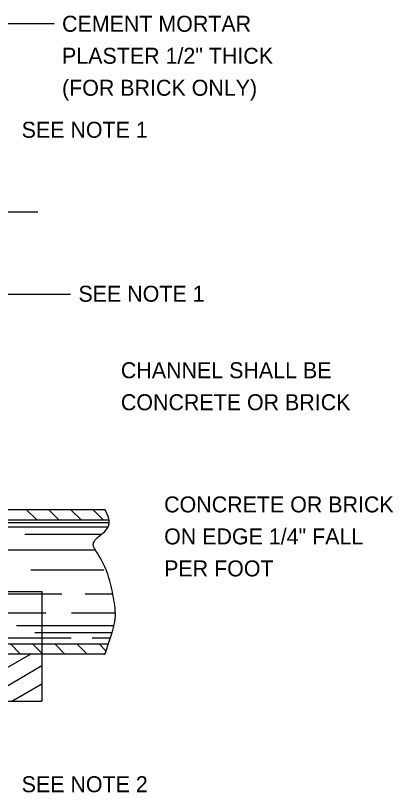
# Model space of a CAD drawing. Extents: x 0.9 to 8, y -0.9 to 9.3.
# Drawn here: x 3.564 to 4.98, y 1.262 to 4.176 of the extents above; entities that cross this region are included whole.
import ezdxf

# ---------------------------------------------------------------- set-up
doc = ezdxf.new("R2010")
doc.units = 0
for name, color, linetype in [('DETL-DIMS', 7, 'Continuous'), ('DETL-LINE', 7, 'Continuous'), ('DETL-NOTE', 7, 'Continuous'), ('DETL-PATT', 7, 'Continuous')]:
    doc.layers.add(name, color=color, linetype=linetype)

msp = doc.modelspace()

# ---------------------------------------------------------------- linework, layer by layer
at = {"layer": 'DETL-DIMS'}
for p, q in [((3.7088, 4.145), (3.2487, 4.145)), ((3.7703, 3.1298), (3.3102, 3.1298))]:
    msp.add_line(p, q, dxfattribs=at)
at = {"layer": 'DETL-LINE'}
for p, q in [((2.7912, 3.4397), (3.6474, 3.4397)), ((3.8992, 2.3221), (3.2514, 2.3221)), ((3.2514, 2.2839), (3.9149, 2.2839)), ((3.5161, 2.0157), (3.6631, 2.0157)), ((3.6631, 2.0157), (3.6631, 1.7804)), ((3.2514, 1.8187), (3.9113, 1.8187)), ((3.8984, 1.7804), (3.2514, 1.7804)), ((3.6631, 1.7804), (3.6631, 1.604)), ((1.6043, 1.604), (3.6631, 1.604))]:
    msp.add_line(p, q, dxfattribs=at)
msp.add_spline([(3.8977, 1.7782), (3.9286, 1.8701), (3.9373, 1.9126), (3.9311, 1.9926), (3.8711, 2.1589), (3.8549, 2.1926), (3.9111, 2.2577), (3.9136, 2.2877), (3.8988, 2.3229)], degree=3, dxfattribs=at)
at = {"layer": 'DETL-PATT'}
for p, q in [((3.605, 2.3221), (3.6432, 2.2839)), ((3.6882, 2.3221), (3.7264, 2.2839)), ((3.7714, 2.3221), (3.8096, 2.2839)), ((3.8545, 2.3221), (3.8928, 2.2839)), ((3.4578, 2.2742), (3.915, 2.2742)), ((3.5169, 2.2583), (3.9113, 2.2583)), ((3.5992, 2.2302), (3.8851, 2.2302)), ((3.5366, 2.1722), (3.8647, 2.1722)), ((3.6213, 2.0966), (3.8954, 2.0966)), ((3.416, 2.007), (3.7372, 2.007)), ((3.8253, 2.007), (3.9269, 2.007)), ((3.2514, 1.9349), (3.6769, 1.9349)), ((3.7731, 1.9349), (3.9387, 1.9349)), ((3.5679, 1.8875), (3.9333, 1.8875)), ((3.2514, 1.8418), (3.772, 1.8418)), ((3.6363, 1.8611), (3.9256, 1.8611)), ((3.8508, 1.8418), (3.9191, 1.8418)), ((3.5445, 1.8187), (3.5827, 1.7804)), ((3.6277, 1.8187), (3.6659, 1.7804)), ((3.7109, 1.8187), (3.7491, 1.7804)), ((3.7941, 1.8187), (3.8323, 1.7804)), ((3.8773, 1.8187), (3.9027, 1.7932)), ((3.3144, 1.604), (3.6201, 1.7804)), ((3.4321, 1.604), (3.6631, 1.7374)), ((3.5497, 1.604), (3.6631, 1.6694))]:
    msp.add_line(p, q, dxfattribs=at)

# ---------------------------------------------------------------- texts
at = {"layer": 'DETL-NOTE'}
for s, p in [('CEMENT MORTAR', (3.7382, 4.115)), ('PLASTER 1/2" THICK', (3.7382, 3.995)), ('(FOR BRICK ONLY)', (3.7382, 3.875)), ('SEE NOTE 1', (3.5868, 3.7174)), ('SEE NOTE 1', (3.7997, 3.1024)), ('CHANNEL SHALL BE ', (3.9588, 2.8154)), ('CONCRETE OR BRICK', (3.9588, 2.6954)), ('CONCRETE OR BRICK', (4.1208, 2.3121)), ('ON EDGE 1/4" FALL', (4.1208, 2.1921)), ('PER FOOT', (4.1208, 2.0721)), ('SEE NOTE 2', (3.5868, 1.2626))]:
    msp.add_text(s, height=0.06, dxfattribs=at).set_placement(p)

doc.saveas('drawing.dxf')
